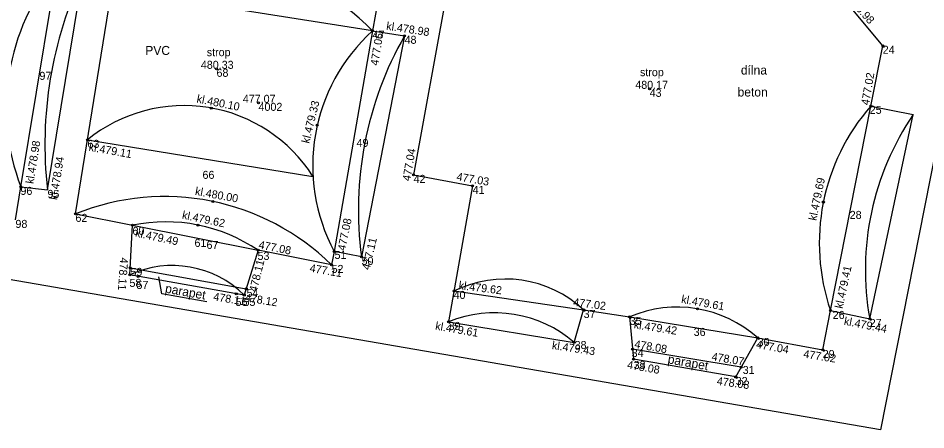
# Model space of a CAD drawing. Extents: x -874376.5 to -874348.6, y -1056301.7 to -1056225.7.
# Drawn here: x -874367.49 to -874358.42, y -1056275.91 to -1056271.79 of the extents above; entities that cross this region are included whole.
import ezdxf

# ---------------------------------------------------------------- set-up
doc = ezdxf.new("R2010")
doc.units = 0
for name, color, linetype in [('Vrstva 1', 7, 'Continuous'), ('Vrstva 2', 7, 'Continuous'), ('Vrstva 3', 7, 'Continuous'), ('Vrstva 57', 7, 'Continuous'), ('Vrstva 6', 7, 'Continuous'), ('Vrstva 60', 7, 'Continuous'), ('Vrstva 61', 7, 'Continuous'), ('Vrstva 62', 7, 'Continuous')]:
    doc.layers.add(name, color=color, linetype=linetype)

msp = doc.modelspace()

# ---------------------------------------------------------------- linework, layer by layer
at = {"layer": 'Vrstva 1'}
for p, q in [((-874367.4658, -1056273.4807), (-874367.1071, -1056271.3006)), ((-874363.95, -1056271.92), (-874366.5563, -1056271.5085)), ((-874363.95, -1056271.92), (-874364.333, -1056274.1269)), ((-874359.3723, -1056274.7164), (-874358.9687, -1056272.6717)), ((-874366.8, -1056273.01), (-874364.5459, -1056273.3755)), ((-874366.3492, -1056273.8637), (-874365.0942, -1056274.1138)), ((-874366.3737, -1056274.2901), (-874365.2119, -1056274.499)), ((-874366.0563, -1056274.5488), (-874366.0879, -1056274.38)), ((-874365.6051, -1056274.6279), (-874366.0563, -1056274.5488)), ((-874363.1354, -1056274.5206), (-874361.84, -1056274.71)), ((-874361.38, -1056274.78), (-874360.1, -1056274.99)), ((-874360.2649, -1056275.2827), (-874361.3508, -1056275.1018))]:
    msp.add_line(p, q, dxfattribs=at)
at = {"layer": 'Vrstva 2'}
for p, q in [((-874366.92, -1056273.75), (-874366.43, -1056270.73)), ((-874363.81, -1056271.13), (-874363.95, -1056271.92)), ((-874363.13, -1056271.11), (-874363.54, -1056273.36)), ((-874367.2, -1056273.51), (-874366.8424, -1056271.3412)), ((-874358.85, -1056272.07), (-874359.23, -1056271.61)), ((-874358.07, -1056271.84), (-874358.8719, -1056275.9085)), ((-874363.95, -1056271.92), (-874363.63, -1056271.97)), ((-874363.63, -1056271.97), (-874364.06, -1056274.18)), ((-874358.9687, -1056272.6717), (-874358.85, -1056272.07)), ((-874358.9687, -1056272.6717), (-874358.5445, -1056272.7563)), ((-874358.98, -1056274.8), (-874358.5445, -1056272.7563)), ((-874358.8719, -1056275.9085), (-874376.451, -1056272.8758)), ((-874363.54, -1056273.36), (-874362.95, -1056273.47)), ((-874367.52, -1056273.81), (-874367.4658, -1056273.4811)), ((-874367.4658, -1056273.4811), (-874367.2, -1056273.51)), ((-874362.95, -1056273.47), (-874363.19, -1056274.83)), ((-874366.92, -1056273.75), (-874366.3492, -1056273.8637)), ((-874366.3777, -1056274.3597), (-874366.3492, -1056273.8637)), ((-874365.0942, -1056274.1138), (-874365.2319, -1056274.5634)), ((-874364.36, -1056274.26), (-874365.0942, -1056274.1138)), ((-874364.333, -1056274.1269), (-874364.36, -1056274.26)), ((-874364.06, -1056274.18), (-874364.333, -1056274.1269)), ((-874365.2319, -1056274.5634), (-874366.3779, -1056274.3597)), ((-874361.9345, -1056275.0356), (-874361.84, -1056274.71)), ((-874361.84, -1056274.71), (-874361.38, -1056274.78)), ((-874359.45, -1056275.11), (-874359.3723, -1056274.7164)), ((-874359.3723, -1056274.7164), (-874358.98, -1056274.8)), ((-874363.19, -1056274.83), (-874361.9345, -1056275.0356)), ((-874361.38, -1056274.78), (-874361.3417, -1056275.2017)), ((-874360.32, -1056275.38), (-874360.1, -1056274.99)), ((-874360.1, -1056274.99), (-874359.45, -1056275.11)), ((-874360.32, -1056275.38), (-874361.3416, -1056275.2017))]:
    msp.add_line(p, q, dxfattribs=at)
at = {"layer": 'Vrstva 3'}
for centre, radius, start, end in [((-874365.4232, -1056272.6972), 2.1878, 140.32912, 200.98486), ((-874365.5295, -1056273.465), 2.2095, 44.37742, 117.69044), ((-874363.1881, -1056273.0576), 4.0373, 154.84053, 186.4337), ((-874362.7307, -1056273.2683), 1.8178, 132.12337, 208.19806), ((-874360.5894, -1056273.7085), 3.5025, 150.24176, 187.73728), ((-874365.8355, -1056274.1952), 1.528, 32.44011, 129.13784), ((-874357.4047, -1056274.0426), 2.0798, 138.76574, 198.90233), ((-874356.2645, -1056274.3104), 2.7593, 145.7241, 190.2206), ((-874366.0286, -1056275.9555), 2.3789, 45.45875, 112.00748), ((-874366.0167, -1056275.4692), 1.6395, 55.75902, 101.69814), ((-874365.951, -1056275.2834), 1.0176, 45.05299, 114.80641), ((-874362.6247, -1056275.5522), 1.1511, 47.0249, 116.33736), ((-874362.7289, -1056275.9502), 1.2114, 49.02286, 112.37302), ((-874360.904, -1056275.8843), 1.2026, 48.04593, 113.31989)]:
    msp.add_arc(centre, radius, start, end, dxfattribs=at)
at = {"layer": 'Vrstva 57'}
for centre in [(-874363.95, -1056271.92), (-874363.63, -1056271.97), (-874358.85, -1056272.07), (-874365.51, -1056272.3), (-874361.18, -1056272.5), (-874365.09, -1056272.64), (-874358.9687, -1056272.6717), (-874365.5618, -1056272.6925), (-874364.5034, -1056272.8626), (-874366.8, -1056273.01), (-874363.54, -1056273.36), (-874367.4658, -1056273.4807), (-874362.95, -1056273.47), (-874365.5477, -1056273.6261), (-874359.4434, -1056273.6314), (-874366.92, -1056273.75), (-874366.3492, -1056273.8637), (-874365.695, -1056273.8615), (-874365.0942, -1056274.1138), (-874364.333, -1056274.1269), (-874364.06, -1056274.18), (-874366.3733, -1056274.2897), (-874364.36, -1056274.26), (-874366.3777, -1056274.3597), (-874366.2934, -1056274.3746), (-874365.2122, -1056274.4992), (-874365.3121, -1056274.5496), (-874365.2319, -1056274.5634), (-874363.1354, -1056274.5208), (-874361.84, -1056274.71), (-874360.702, -1056274.6988), (-874359.3723, -1056274.7164), (-874363.19, -1056274.83), (-874361.38, -1056274.78), (-874358.98, -1056274.8), (-874361.9345, -1056275.0356), (-874360.1, -1056274.99), (-874361.3508, -1056275.1018), (-874359.45, -1056275.11), (-874361.3416, -1056275.2017), (-874360.2649, -1056275.2827), (-874360.32, -1056275.38)]:
    msp.add_circle(centre, 0.01, dxfattribs=at)
at = {"layer": 'Vrstva 60'}
for p, q in [((-874363.95, -1056271.92), (-874363.95, -1056271.92)), ((-874363.63, -1056271.97), (-874363.63, -1056271.97)), ((-874358.85, -1056272.07), (-874358.85, -1056272.07)), ((-874365.51, -1056272.3), (-874365.51, -1056272.3)), ((-874367.28, -1056272.33), (-874367.28, -1056272.33)), ((-874361.18, -1056272.5), (-874361.18, -1056272.5)), ((-874365.09, -1056272.64), (-874365.09, -1056272.64)), ((-874358.98, -1056272.67), (-874358.98, -1056272.67)), ((-874366.8, -1056273.01), (-874366.8, -1056273.01)), ((-874364.11, -1056273), (-874364.11, -1056273)), ((-874365.65, -1056273.32), (-874365.65, -1056273.32)), ((-874363.54, -1056273.36), (-874363.54, -1056273.36)), ((-874367.47, -1056273.48), (-874367.47, -1056273.48)), ((-874362.95, -1056273.47), (-874362.95, -1056273.47)), ((-874367.2, -1056273.51), (-874367.2, -1056273.51)), ((-874366.92, -1056273.75), (-874366.92, -1056273.75)), ((-874359.18, -1056273.72), (-874359.18, -1056273.72)), ((-874366.35, -1056273.88), (-874366.35, -1056273.88)), ((-874365.73, -1056274), (-874365.73, -1056274)), ((-874365.61, -1056274.02), (-874365.61, -1056274.02)), ((-874365.1, -1056274.13), (-874365.1, -1056274.13)), ((-874364.33, -1056274.12), (-874364.33, -1056274.12)), ((-874364.06, -1056274.18), (-874364.06, -1056274.18)), ((-874366.37, -1056274.29), (-874366.37, -1056274.29)), ((-874364.36, -1056274.26), (-874364.36, -1056274.26)), ((-874366.38, -1056274.4), (-874366.38, -1056274.4)), ((-874366.31, -1056274.42), (-874366.31, -1056274.42)), ((-874365.21, -1056274.5), (-874365.21, -1056274.5)), ((-874363.14, -1056274.52), (-874363.14, -1056274.52)), ((-874365.32, -1056274.59), (-874365.32, -1056274.59)), ((-874365.24, -1056274.59), (-874365.24, -1056274.59)), ((-874361.84, -1056274.71), (-874361.84, -1056274.71)), ((-874359.35, -1056274.72), (-874359.35, -1056274.72)), ((-874363.19, -1056274.83), (-874363.19, -1056274.83)), ((-874361.38, -1056274.78), (-874361.38, -1056274.78)), ((-874358.98, -1056274.8), (-874358.98, -1056274.8)), ((-874360.74, -1056274.89), (-874360.74, -1056274.89)), ((-874361.93, -1056275.02), (-874361.93, -1056275.02)), ((-874360.1, -1056274.99), (-874360.1, -1056274.99)), ((-874361.36, -1056275.1), (-874361.36, -1056275.1)), ((-874359.45, -1056275.11), (-874359.45, -1056275.11)), ((-874361.34, -1056275.22), (-874361.34, -1056275.22)), ((-874360.25, -1056275.27), (-874360.25, -1056275.27)), ((-874360.32, -1056275.38), (-874360.32, -1056275.38))]:
    msp.add_line(p, q, dxfattribs=at)

# ---------------------------------------------------------------- texts
at = {"layer": 'Vrstva 6'}
for s, p in [('PVC', (-874366.2221, -1056272.1614)), ('dílna', (-874360.2679, -1056272.3573)), ('beton', (-874360.301, -1056272.5769))]:
    msp.add_text(s, height=0.09, dxfattribs=at).set_placement(p)
for p in [(-874366.0288, -1056274.5364), (-874361.0044, -1056275.243)]:
    msp.add_text('parapet', height=0.09, rotation=350.01228, dxfattribs=at).set_placement(p)
at = {"layer": 'Vrstva 61'}
for s, p in [('47', (-874363.95, -1056272)), ('48', (-874363.63, -1056272.05)), ('24', (-874358.85, -1056272.15)), ('68', (-874365.51, -1056272.38)), ('97', (-874367.28, -1056272.41)), ('43', (-874361.18, -1056272.58)), ('4002', (-874365.09, -1056272.72)), ('25', (-874358.98, -1056272.75)), ('63', (-874366.8, -1056273.09)), ('49', (-874364.11, -1056273.08)), ('66', (-874365.65, -1056273.4)), ('42', (-874363.54, -1056273.44)), ('96', (-874367.47, -1056273.56)), ('41', (-874362.95, -1056273.55)), ('95', (-874367.2, -1056273.59)), ('62', (-874366.92, -1056273.83)), ('28', (-874359.18, -1056273.8)), ('98', (-874367.52, -1056273.89)), ('60', (-874366.35, -1056273.96)), ('61', (-874365.73, -1056274.08)), ('67', (-874365.61, -1056274.1)), ('53', (-874365.1, -1056274.21)), ('51', (-874364.33, -1056274.2)), ('50', (-874364.06, -1056274.26)), ('59', (-874366.37, -1056274.37)), ('52', (-874364.36, -1056274.34)), ('58', (-874366.38, -1056274.48)), ('57', (-874366.31, -1056274.5)), ('54', (-874365.21, -1056274.58)), ('40', (-874363.14, -1056274.6)), ('56', (-874365.32, -1056274.67)), ('55', (-874365.24, -1056274.67)), ('37', (-874361.84, -1056274.79)), ('26', (-874359.35, -1056274.8)), ('39', (-874363.19, -1056274.91)), ('35', (-874361.38, -1056274.86)), ('27', (-874358.98, -1056274.88)), ('36', (-874360.74, -1056274.97)), ('38', (-874361.93, -1056275.1)), ('30', (-874360.1, -1056275.07)), ('34', (-874361.36, -1056275.18)), ('29', (-874359.45, -1056275.19)), ('33', (-874361.34, -1056275.3)), ('31', (-874360.25, -1056275.35)), ('32', (-874360.32, -1056275.46))]:
    msp.add_text(s, height=0.08, dxfattribs=at).set_placement(p)
at = {"layer": 'Vrstva 62'}
for s, rotation, p in [('476.98', 311.89315, (-874359.2033, -1056271.616)), ('kl.478.98', 351.33839, (-874363.8166, -1056271.9084)), ('477.06', 80.78463, (-874363.8941, -1056272.2715)), ('477.02', 80.31458, (-874358.988, -1056272.6679)), ('kl.480.10', 348.67364, (-874365.7132, -1056272.6348)), ('kl.479.33', 76.17518, (-874364.5838, -1056273.0508)), ('kl.478.98', 80.82622, (-874367.3401, -1056273.4534)), ('kl.479.11', 350.0435, (-874366.791, -1056273.1182)), ('477.04', 80.06774, (-874363.5743, -1056273.4263)), ('kl.478.94', 80.6131, (-874367.1043, -1056273.6141)), ('477.03', 350.36366, (-874363.1146, -1056273.4144)), ('kl.479.69', 78.2386, (-874359.5146, -1056273.8223)), ('kl.480.00', 349.71003, (-874365.7287, -1056273.5597)), ('kl.479.62', 348.16702, (-874365.8592, -1056273.7963)), ('477.08', 78.54796, (-874364.2231, -1056274.1231)), ('kl.479.49', 348.17159, (-874366.3269, -1056273.9762)), ('477.08', 348.83879, (-874365.094, -1056274.0945)), ('477.11', 77.0649, (-874363.979, -1056274.3154)), ('478.11', 266.04529, (-874366.4726, -1056274.1843)), ('478.11', 76.11685, (-874365.1083, -1056274.5367)), ('477.11', 350.31193, (-874364.5834, -1056274.3285)), ('kl.479.41', 77.85619, (-874359.2518, -1056274.7015)), ('kl.479.62', 352.90325, (-874363.0928, -1056274.5013)), ('478.11', 350.8605, (-874365.5458, -1056274.6138)), ('478.12', 351.06412, (-874365.2298, -1056274.6242)), ('kl.479.61', 349.86127, (-874360.8685, -1056274.6386)), ('477.02', 352.73022, (-874361.9474, -1056274.6699)), ('kl.479.61', 350.23788, (-874363.3273, -1056274.9064)), ('kl.479.42', 351.30797, (-874361.3418, -1056274.8931)), ('kl.479.44', 348.9948, (-874359.2422, -1056274.8574)), ('kl.479.43', 351.54746, (-874362.1606, -1056275.1003)), ('478.08', 350.37048, (-874361.3363, -1056275.088)), ('477.04', 349.85622, (-874360.1188, -1056275.0903)), ('477.02', 350.91757, (-874359.6477, -1056275.1858)), ('478.08', 350.20429, (-874361.4094, -1056275.2941)), ('478.07', 350.60199, (-874360.5646, -1056275.2127)), ('478.08', 352.25802, (-874360.5126, -1056275.4575))]:
    msp.add_text(s, height=0.08, rotation=rotation, dxfattribs=at).set_placement(p)
for s, p in [('strop', (-874365.6073, -1056272.1738)), ('480.33', (-874365.6664, -1056272.3)), ('strop', (-874361.2766, -1056272.3736)), ('480.17', (-874361.3236, -1056272.5)), ('477.07', (-874365.2471, -1056272.64))]:
    msp.add_text(s, height=0.08, dxfattribs=at).set_placement(p)

doc.saveas('drawing.dxf')
